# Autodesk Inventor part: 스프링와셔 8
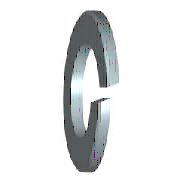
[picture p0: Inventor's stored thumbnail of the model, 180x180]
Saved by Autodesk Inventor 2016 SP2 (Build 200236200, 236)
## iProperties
IsCustomPart: 1
Created: 2012-02
Part Number: 스프링와셔 8
Material: 강철, 연강
Description: 스프링 잠금 와셔
Document SubType Name: Modeling
Standard: KS B 1324
Designer: mduedu
Standards Organization: KS
Language: ko-KR
Size Designation: 번호 3 - 8
Categories: <MemberInstance><Categories><Category DisplayName="조임쇠" InternalName="e4da775c-781d-43d5-af7c-5136215cf5a6" Mnemonic="FSTN"><Category DisplayName="와셔" InternalN
Density: 1 g/cm^3
Appearance: 파란색 - 벽 페인트 - 광택
Author: mduedu
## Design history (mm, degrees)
sketch "스케치1"
  geometry: C1 r 7.4 at (0, 0); C2 r 4.1 at (0, 0); 1 further point
  constraints: 2 centre point, 2 coincident
  dimensions: "d0" = 8.2 diameter of C2 (= SD1); "d1" = 14.8 diameter of C1 (= SD2)
extrude "본체" new body sketch "스케치1" distance "d2" = 2.5 (= SD); taper "d3" = 0 deg
sketch "스케치2"
  geometry: L1 (0, -4.1)-(0, 4.1) reference; L2 (2.5, 7.4)-(2.5, -7.4) reference; L3 (-1.2, 0)-(7.2, 0) reference; L4 (0, -0.5)-(2.5, 0.41); L5 (0, 0.5)-(2.5, 1.41)
  constraints: 4 end point, 4 point on line, 1 parallel
  dimensions: "d4" = 0.5 distance from line of L3 L4.start (= 0.2 x SD); "d5" = 0.5 distance from line of L3 L5.start (= 0.2 x SD); "d6" = 70 deg angle of L2 L4 (= FAWI)
extrude "절단부" cut sketch "스케치2" stored distance "d7" = 2.5 (= SD); taper "d8" = 0 deg
workaxis "Work Axis1"
workplane "Work Plane1"
body "Solid1"
other parameters: "SD1" = 8.2 [user parameter; used in 1 equation term], "SD2" = 14.8 [user parameter; used in 1 equation term], "SD" = 2.5 [user parameter; used in 4 equation terms], "FAWI" = 70 deg [user parameter; used in 1 equation term], "d9" = 0, "d10" = 0, "d11" = 0, "d12" = 0, "SDI" = 3.3 [user parameter], "NND" = 8 [user parameter]
